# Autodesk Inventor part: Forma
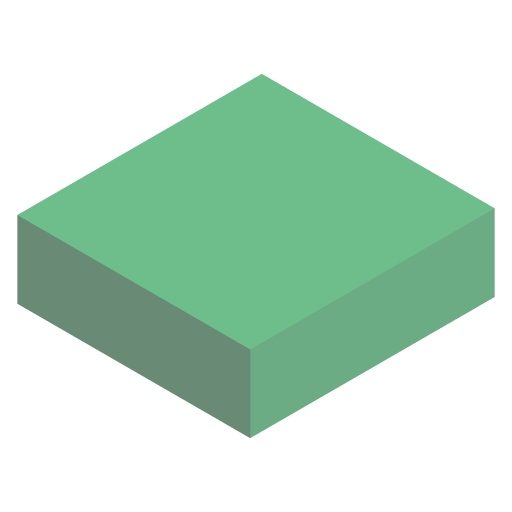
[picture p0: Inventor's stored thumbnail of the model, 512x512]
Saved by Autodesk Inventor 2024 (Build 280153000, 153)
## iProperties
Company: ATC
Shininess: 20.0
Length Units: 11269
Angle Units: 11279
Time Units: 11290
Mass Units: 11283
Length Display Precision: 3
Angle Display Precision: 2
Compacted: True
Created: 2023-03
Part Number: Forma
Document SubType Name: Modeling
Designer: Andrzej Jaskulski
Material: Kurs-AJ
Density: 1 g/cm^3
Appearance: Przezroczyste - zielone 1
Checked By: A.J.
Engr Approved By: Andrzej Jaskulski
Mfg Approved By: Andrzej Jaskulski
Authority: A.J.
Density: 0.0
Volumn: 0.0
Area: 0.0
PropertySet Name: Model Information
Control State: 0
Master: False
Checked Out: False
Title: A.J.: Kurs R2024-MEP
Author: Andrzej Jaskulski
Revision Number: 1/24
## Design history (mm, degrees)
sketch "Sketch1"
  geometry: L1 (-49, 50)-(51, 50); L2 (51, 50)-(51, -55); L3 (51, -55)-(-49, -55); L4 (-49, -55)-(-49, 50)
  constraints: 8 end point, 2 parallel, 1 horizontal, 1 perpendicular
extrude "Extrusion1" new body sketch "Sketch1" distance "d4" = 33; taper "d5" = 0 deg
node "Bryła1"
node "Korpusy bryłowe"
node "Korpusy powierzchniowe"
